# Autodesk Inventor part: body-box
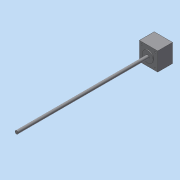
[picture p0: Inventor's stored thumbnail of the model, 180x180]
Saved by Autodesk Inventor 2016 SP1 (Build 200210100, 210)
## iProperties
Created: 2016-06
Part Number: body-box
Material: Generic
Document SubType Name: Modeling
Designer: Mohamed A.
Density: 1 g/cm^3
Appearance: Default
Author: Mohamed A.
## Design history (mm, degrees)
sketch "Sketch1"
  geometry: L1 (-21, 21)-(21, 21); L2 (21, 21)-(21, -21); L3 (21, -21)-(-21, -21); L4 (-21, -21)-(-21, 21); L5 (-21, 21)-(21, -21); L6 (21, 21)-(-21, -21); 1 further point
  constraints: 12 end point, 2 midpoint, 2 parallel, 1 horizontal, 1 perpendicular
  dimensions: "d0" = 42 distance of L2.end L3.end; "d1" = 42 distance of L1.end L2.end
extrude "Extrusion1" new body sketch "Sketch1" distance "d2" = 34; taper "d3" = 0 deg
sketch "Sketch2"
  geometry: C1 r 1.5 at (-15.5, 15.5); C2 r 1.5 at (15.5, 15.5); C3 r 1.5 at (15.5, -15.5); C4 r 1.5 at (-15.5, -15.5); 1 further point
  constraints: 4 centre point
  dimensions: "d4" = 3 diameter of C1; "d5" = 3 diameter of C2; "d6" = 3 diameter of C3; "d7" = 3 diameter of C4; "d8" = 31 distance of C1.centre C2.centre; "d9" = 31 distance of C3.centre C2.centre; "d10" = 31 distance of C1.centre C4.centre (= d9); "d11" = 31 distance of C4.centre C3.centre (= d8); "d12" = 15.5 horizontal distance of C2.centre point (0, 0) (= 0.5 x d8); "d13" = 15.5 horizontal distance of C1.centre point (0, 0) (= 0.5 x d10); "d14" = 15.5 horizontal distance of point (0, 0) C2.centre (= d13); "d15" = 15.5 horizontal distance of point (0, 0) C4.centre
extrude "Extrusion2" cut sketch "Sketch2" distance "d17" = 5; taper "d18" = 0 deg
sketch "Sketch3"
  geometry: C1 r 12.5 at (0, 0); 1 further point
  constraints: 1 centre point, 1 coincident
  dimensions: "d19" = 25 diameter of C1
extrude "Extrusion3" join sketch "Sketch3" distance "d20" = 2; taper "d21" = 0 deg
sketch "Sketch4"
  geometry: C1 r 3.5 at (0, 0); 1 further point
  constraints: 1 centre point, 1 coincident
  dimensions: "d22" = 7 diameter of C1
extrude "Extrusion4" join sketch "Sketch4" distance "d23" = 300; taper "d24" = 0 deg
body "Solid1"
